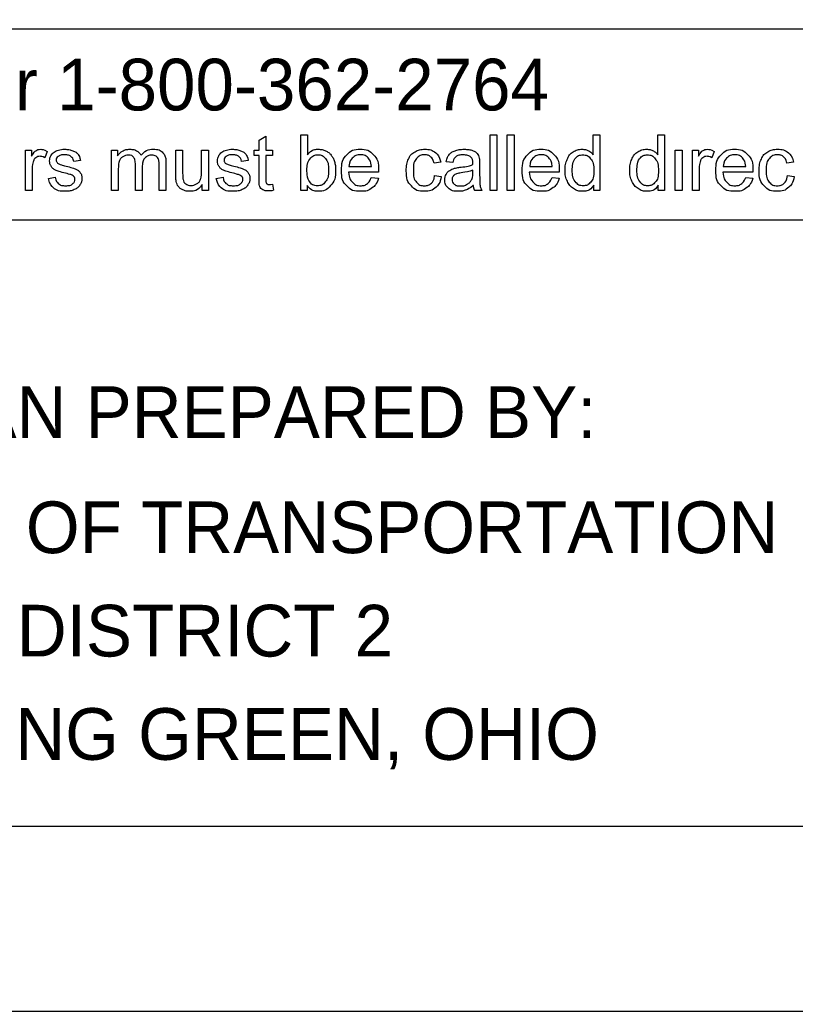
# Model space of a CAD drawing. Extents: x -5.6 to 34, y 0 to 22.
# Drawn here: x 4.575 to 6.676, y 0 to 2.686 of the extents above; entities that cross this region are included whole.
import ezdxf

# ---------------------------------------------------------------- set-up
doc = ezdxf.new("R2010")
doc.units = 0
for name, color, linetype in [('SH_Border', 7, 'Continuous'), ('SH_Cut_Line', 7, 'Continuous'), ('SH_Data', 7, 'Continuous'), ('SH_Text', 7, 'Continuous')]:
    doc.layers.add(name, color=color, linetype=linetype)

msp = doc.modelspace()

# ---------------------------------------------------------------- linework, layer by layer
at = {"layer": 'SH_Border'}
msp.add_lwpolyline([(1.5, 21.5), (33.5, 21.5), (33.5, 0.5), (1.5, 0.5)], close=True, dxfattribs=at)
at = {"layer": 'SH_Cut_Line'}
msp.add_lwpolyline([(0, 0), (34, 0), (34, 22), (0, 22)], close=True, dxfattribs=at)
at = {"layer": 'SH_Data'}
for p, q in [((7.2275, 2.6607), (2.9775, 2.6607)), ((7.2275, 2.1428), (2.9775, 2.1428))]:
    msp.add_line(p, q, dxfattribs=at)
at = {"layer": 'SH_Text'}
for points in [[(5.2233, 2.2558), (5.2233, 2.3185), (5.2097, 2.3185), (5.2097, 2.3328), (5.2233, 2.3328), (5.2233, 2.3597), (5.2417, 2.3708), (5.2417, 2.3328), (5.2601, 2.3328), (5.2601, 2.3185), (5.2417, 2.3185), (5.2417, 2.2547)], [(5.3534, 2.2239), (5.3363, 2.2239), (5.3363, 2.3741), (5.3548, 2.3741), (5.3548, 2.3206)], [(5.8491, 2.2239), (5.8491, 2.3741), (5.8675, 2.3741), (5.8675, 2.2239), (5.8491, 2.2239)], [(5.8956, 2.2239), (5.8956, 2.3741), (5.9141, 2.3741), (5.9141, 2.2239), (5.8956, 2.2239)], [(6.1285, 2.3202), (6.1285, 2.3741), (6.1469, 2.3741), (6.1469, 2.2239), (6.1299, 2.2239)], [(6.3034, 2.3202), (6.3034, 2.3741), (6.3218, 2.3741), (6.3218, 2.2239), (6.3048, 2.2239)], [(4.5904, 2.2239), (4.5904, 2.3328), (4.607, 2.3328), (4.607, 2.3163)], [(4.6495, 2.3293), (4.643, 2.3122)], [(4.8236, 2.2239), (4.8236, 2.3328), (4.8401, 2.3328), (4.8401, 2.3174)], [(4.9979, 2.2654), (4.9979, 2.3328), (5.0164, 2.3328), (5.0164, 2.2724)], [(5.0676, 2.2745), (5.0676, 2.3328), (5.0861, 2.3328), (5.0861, 2.2239), (5.0696, 2.2239)], [(6.3509, 2.2239), (6.3509, 2.3328), (6.3693, 2.3328), (6.3693, 2.2239), (6.3509, 2.2239)], [(6.3971, 2.2239), (6.3971, 2.3328), (6.4137, 2.3328), (6.4137, 2.3163)], [(6.4562, 2.3293), (6.4497, 2.3122)], [(4.7394, 2.3046), (4.7213, 2.3022)], [(4.9067, 2.2871), (4.9067, 2.2239), (4.8883, 2.2239), (4.8883, 2.2946)], [(4.9711, 2.2986), (4.9711, 2.2239), (4.9527, 2.2239), (4.9527, 2.2924)], [(5.194, 2.3046), (5.1759, 2.3022)], [(5.4669, 2.2887), (5.5277, 2.2887)], [(5.7154, 2.3007), (5.6974, 2.298)], [(5.7479, 2.2992), (5.7298, 2.3016)], [(5.8209, 2.2941), (5.8209, 2.2695)], [(5.9565, 2.2887), (6.0173, 2.2887)], [(6.481, 2.2887), (6.5418, 2.2887)], [(6.6712, 2.3007), (6.6532, 2.298)], [(4.6088, 2.2809), (4.6088, 2.2239), (4.5904, 2.2239)], [(4.653, 2.2564), (4.6712, 2.2593)], [(4.842, 2.2803), (4.842, 2.2239), (4.8236, 2.2239)], [(5.1076, 2.2564), (5.1258, 2.2593)], [(5.547, 2.2736), (5.4659, 2.2736)], [(5.5275, 2.2591), (5.5465, 2.2567)], [(5.699, 2.2638), (5.7171, 2.2613)], [(5.8023, 2.2718), (5.8024, 2.2785)], [(6.0366, 2.2736), (5.9555, 2.2736)], [(6.0171, 2.2591), (6.0361, 2.2567)], [(6.4155, 2.2809), (6.4155, 2.2239), (6.3971, 2.2239)], [(6.5611, 2.2736), (6.48, 2.2736)], [(6.5416, 2.2591), (6.5606, 2.2567)], [(6.6548, 2.2638), (6.6729, 2.2613)], [(5.0696, 2.2239), (5.0696, 2.24)], [(5.2601, 2.2404), (5.2628, 2.2241)], [(5.3534, 2.2375), (5.3534, 2.2239)], [(6.1299, 2.2239), (6.1299, 2.2376)], [(6.3048, 2.2239), (6.3048, 2.2376)], [(5.8267, 2.2239), (5.8075, 2.2239)]]:
    msp.add_lwpolyline(points, dxfattribs=at)
for points, degree in [([(4.607, 2.3163), (4.6133, 2.3278), (4.6187, 2.3315), (4.6241, 2.3352), (4.6305, 2.3352), (4.6398, 2.3352), (4.6495, 2.3293)], 3), ([(4.643, 2.3122), (4.6363, 2.3162), (4.6295, 2.3162), (4.6235, 2.3162), (4.6187, 2.3125), (4.6139, 2.3089), (4.6119, 2.3024), (4.6088, 2.2926), (4.6088, 2.2809)], 3), ([(4.7213, 2.3022), (4.7201, 2.3106), (4.7142, 2.3153), (4.7083, 2.3201), (4.6975, 2.3201), (4.6848, 2.3201), (4.6794, 2.3159), (4.6739, 2.3116), (4.6739, 2.306), (4.6739, 2.3024), (4.6762, 2.2995), (4.6785, 2.2966), (4.6833, 2.2946), (4.686, 2.2936), (4.6996, 2.2899), (4.7192, 2.2847), (4.7269, 2.2813), (4.7347, 2.278), (4.7391, 2.2717), (4.7435, 2.2653), (4.7435, 2.2559), (4.7435, 2.2467), (4.7381, 2.2386), (4.7327, 2.2304), (4.7226, 2.226), (4.7124, 2.2215), (4.6996, 2.2215), (4.6784, 2.2215), (4.6672, 2.2303), (4.6561, 2.2391), (4.653, 2.2564)], 3), ([(4.6712, 2.2593), (4.6727, 2.2483), (4.6798, 2.2425), (4.6868, 2.2366), (4.6995, 2.2366), (4.7122, 2.2366), (4.7184, 2.2418), (4.7245, 2.247), (4.7245, 2.254), (4.7245, 2.2602), (4.7191, 2.2638), (4.7153, 2.2663), (4.7002, 2.2701), (4.6799, 2.2752), (4.672, 2.2789), (4.6642, 2.2827), (4.6601, 2.2893), (4.6561, 2.2959), (4.6561, 2.3038), (4.6561, 2.3111), (4.6594, 2.3173), (4.6628, 2.3235), (4.6685, 2.3276), (4.6728, 2.3308), (4.6803, 2.333), (4.6877, 2.3352), (4.6962, 2.3352), (4.709, 2.3352), (4.7187, 2.3315), (4.7284, 2.3278), (4.733, 2.3215), (4.7377, 2.3152), (4.7394, 2.3046)], 3), ([(4.8401, 2.3174), (4.8452, 2.3254), (4.8537, 2.3303), (4.8622, 2.3352), (4.8731, 2.3352), (4.8852, 2.3352), (4.8929, 2.3301), (4.9007, 2.3251), (4.9038, 2.3161), (4.9168, 2.3352), (4.9375, 2.3352), (4.9537, 2.3352), (4.9624, 2.3262), (4.9711, 2.3172), (4.9711, 2.2986)], 3), ([(4.8883, 2.2946), (4.8883, 2.3069), (4.8838, 2.313), (4.8793, 2.3191), (4.869, 2.3191), (4.8612, 2.3191), (4.8546, 2.315), (4.848, 2.311), (4.845, 2.3031), (4.842, 2.2952), (4.842, 2.2803)], 3), ([(4.9527, 2.2924), (4.9527, 2.3035), (4.9509, 2.3083), (4.9491, 2.3132), (4.9444, 2.3162), (4.9397, 2.3191), (4.9333, 2.3191), (4.9219, 2.3191), (4.9143, 2.3115), (4.9067, 2.3039), (4.9067, 2.2871)], 3), ([(5.1759, 2.3022), (5.1747, 2.3106), (5.1688, 2.3153), (5.1629, 2.3201), (5.1521, 2.3201), (5.1394, 2.3201), (5.1339, 2.3159), (5.1285, 2.3116), (5.1285, 2.306), (5.1285, 2.3024), (5.1308, 2.2995), (5.133, 2.2966), (5.1378, 2.2946), (5.1406, 2.2936), (5.1542, 2.2899), (5.1737, 2.2847), (5.1815, 2.2813), (5.1893, 2.278), (5.1937, 2.2717), (5.1981, 2.2653), (5.1981, 2.2559), (5.1981, 2.2467), (5.1927, 2.2386), (5.1873, 2.2304), (5.1772, 2.226), (5.167, 2.2215), (5.1542, 2.2215), (5.1329, 2.2215), (5.1218, 2.2303), (5.1107, 2.2391), (5.1076, 2.2564)], 3), ([(5.1258, 2.2593), (5.1273, 2.2483), (5.1343, 2.2425), (5.1414, 2.2366), (5.154, 2.2366), (5.1668, 2.2366), (5.1729, 2.2418), (5.1791, 2.247), (5.1791, 2.254), (5.1791, 2.2602), (5.1736, 2.2638), (5.1698, 2.2663), (5.1548, 2.2701), (5.1345, 2.2752), (5.1266, 2.2789), (5.1188, 2.2827), (5.1147, 2.2893), (5.1107, 2.2959), (5.1107, 2.3038), (5.1107, 2.3111), (5.114, 2.3173), (5.1173, 2.3235), (5.1231, 2.3276), (5.1274, 2.3308), (5.1348, 2.333), (5.1423, 2.3352), (5.1508, 2.3352), (5.1636, 2.3352), (5.1733, 2.3315), (5.183, 2.3278), (5.1876, 2.3215), (5.1922, 2.3152), (5.194, 2.3046)], 3), ([(5.3532, 2.2792), (5.3532, 2.2596), (5.3585, 2.2509), (5.3672, 2.2366), (5.382, 2.2366), (5.3941, 2.2366), (5.4029, 2.2471), (5.4116, 2.2576), (5.4116, 2.2784), (5.4116, 2.2998), (5.4032, 2.3099), (5.3948, 2.3201), (5.3828, 2.3201), (5.3708, 2.3201), (5.362, 2.3096), (5.3532, 2.299), (5.3532, 2.2792)], 3), ([(5.3548, 2.3206), (5.3664, 2.3352), (5.3846, 2.3352), (5.3946, 2.3352), (5.4036, 2.3311), (5.4125, 2.3271), (5.4183, 2.3198), (5.4241, 2.3124), (5.4274, 2.3021), (5.4306, 2.2918), (5.4306, 2.28), (5.4306, 2.252), (5.4168, 2.2368), (5.403, 2.2215), (5.3836, 2.2215), (5.3644, 2.2215), (5.3534, 2.2375)], 3), ([(5.5465, 2.2567), (5.542, 2.24), (5.5298, 2.2307), (5.5177, 2.2215), (5.4987, 2.2215), (5.4749, 2.2215), (5.4609, 2.2362), (5.4469, 2.2509), (5.4469, 2.2774), (5.4469, 2.3049), (5.461, 2.32), (5.4752, 2.3352), (5.4977, 2.3352), (5.5195, 2.3352), (5.5333, 2.3203), (5.5471, 2.3055), (5.5471, 2.2785), (5.5471, 2.2769), (5.547, 2.2736)], 3), ([(5.5277, 2.2887), (5.5265, 2.3025), (5.5207, 2.3094), (5.5119, 2.3201), (5.4979, 2.3201), (5.4852, 2.3201), (5.4765, 2.3115), (5.4678, 2.303), (5.4669, 2.2887)], 3), ([(5.7171, 2.2613), (5.7141, 2.2427), (5.7019, 2.2321), (5.6896, 2.2215), (5.6718, 2.2215), (5.6495, 2.2215), (5.6359, 2.2361), (5.6223, 2.2507), (5.6223, 2.2779), (5.6223, 2.2955), (5.6282, 2.3088), (5.634, 2.322), (5.646, 2.3286), (5.6579, 2.3352), (5.6719, 2.3352), (5.6897, 2.3352), (5.7009, 2.3262), (5.7122, 2.3172), (5.7154, 2.3007)], 3), ([(5.6974, 2.298), (5.6949, 2.309), (5.6884, 2.3145), (5.6819, 2.3201), (5.6726, 2.3201), (5.6587, 2.3201), (5.65, 2.3101), (5.6413, 2.3001), (5.6413, 2.2784), (5.6413, 2.2565), (5.6497, 2.2466), (5.6581, 2.2366), (5.6717, 2.2366), (5.6825, 2.2366), (5.6898, 2.2433), (5.6971, 2.2499), (5.699, 2.2638)], 3), ([(5.8038, 2.2373), (5.7936, 2.2287), (5.7841, 2.2251), (5.7746, 2.2215), (5.7638, 2.2215), (5.7458, 2.2215), (5.7362, 2.2303), (5.7266, 2.239), (5.7266, 2.2526), (5.7266, 2.2606), (5.7302, 2.2672), (5.7339, 2.2738), (5.7398, 2.2778), (5.7456, 2.2818), (5.753, 2.2838), (5.7584, 2.2853), (5.7694, 2.2866), (5.7917, 2.2893), (5.8023, 2.2929), (5.8024, 2.2967), (5.8024, 2.2978), (5.8024, 2.3091), (5.7971, 2.3137), (5.7901, 2.3199), (5.7762, 2.3199), (5.7632, 2.3199), (5.757, 2.3154), (5.7508, 2.3108), (5.7479, 2.2992)], 3), ([(5.7298, 2.3016), (5.7323, 2.3132), (5.7379, 2.3203), (5.7435, 2.3275), (5.7542, 2.3313), (5.7648, 2.3352), (5.7788, 2.3352), (5.7928, 2.3352), (5.8015, 2.3319), (5.8102, 2.3286), (5.8142, 2.3236), (5.8183, 2.3187), (5.82, 2.3111), (5.8209, 2.3064), (5.8209, 2.2941)], 3), ([(6.0361, 2.2567), (6.0316, 2.24), (6.0194, 2.2307), (6.0072, 2.2215), (5.9883, 2.2215), (5.9644, 2.2215), (5.9505, 2.2362), (5.9365, 2.2509), (5.9365, 2.2774), (5.9365, 2.3049), (5.9506, 2.32), (5.9648, 2.3352), (5.9873, 2.3352), (6.0091, 2.3352), (6.0229, 2.3203), (6.0367, 2.3055), (6.0367, 2.2785), (6.0367, 2.2769), (6.0366, 2.2736)], 3), ([(6.0173, 2.2887), (6.0161, 2.3025), (6.0103, 2.3094), (6.0015, 2.3201), (5.9875, 2.3201), (5.9748, 2.3201), (5.9661, 2.3115), (5.9574, 2.303), (5.9565, 2.2887)], 3), ([(6.1299, 2.2376), (6.1195, 2.2215), (6.0995, 2.2215), (6.0865, 2.2215), (6.0755, 2.2287), (6.0646, 2.2359), (6.0586, 2.2487), (6.0526, 2.2616), (6.0526, 2.2782), (6.0526, 2.2945), (6.0581, 2.3078), (6.0635, 2.321), (6.0743, 2.3281), (6.0852, 2.3352), (6.0986, 2.3352), (6.1084, 2.3352), (6.116, 2.331), (6.1237, 2.3269), (6.1285, 2.3202)], 3), ([(6.0716, 2.2782), (6.0716, 2.2573), (6.0805, 2.247), (6.0893, 2.2366), (6.1012, 2.2366), (6.1133, 2.2366), (6.1218, 2.2465), (6.1302, 2.2564), (6.1302, 2.2767), (6.1302, 2.299), (6.1216, 2.3095), (6.113, 2.3199), (6.1004, 2.3199), (6.0881, 2.3199), (6.0799, 2.3099), (6.0716, 2.2999), (6.0716, 2.2782)], 3), ([(6.3048, 2.2376), (6.2944, 2.2215), (6.2743, 2.2215), (6.2613, 2.2215), (6.2504, 2.2287), (6.2395, 2.2359), (6.2335, 2.2487), (6.2275, 2.2616), (6.2275, 2.2782), (6.2275, 2.2945), (6.2329, 2.3078), (6.2384, 2.321), (6.2492, 2.3281), (6.26, 2.3352), (6.2734, 2.3352), (6.2832, 2.3352), (6.2909, 2.331), (6.2986, 2.3269), (6.3034, 2.3202)], 3), ([(6.2465, 2.2782), (6.2465, 2.2573), (6.2553, 2.247), (6.2641, 2.2366), (6.2761, 2.2366), (6.2882, 2.2366), (6.2967, 2.2465), (6.3051, 2.2564), (6.3051, 2.2767), (6.3051, 2.299), (6.2965, 2.3095), (6.2879, 2.3199), (6.2753, 2.3199), (6.263, 2.3199), (6.2548, 2.3099), (6.2465, 2.2999), (6.2465, 2.2782)], 3), ([(6.4137, 2.3163), (6.4201, 2.3278), (6.4254, 2.3315), (6.4308, 2.3352), (6.4372, 2.3352), (6.4466, 2.3352), (6.4562, 2.3293)], 3), ([(6.4497, 2.3122), (6.443, 2.3162), (6.4363, 2.3162), (6.4302, 2.3162), (6.4255, 2.3125), (6.4207, 2.3089), (6.4186, 2.3024), (6.4155, 2.2926), (6.4155, 2.2809)], 3), ([(6.5606, 2.2567), (6.5561, 2.24), (6.5439, 2.2307), (6.5317, 2.2215), (6.5128, 2.2215), (6.4889, 2.2215), (6.475, 2.2362), (6.461, 2.2509), (6.461, 2.2774), (6.461, 2.3049), (6.4751, 2.32), (6.4892, 2.3352), (6.5118, 2.3352), (6.5336, 2.3352), (6.5474, 2.3203), (6.5612, 2.3055), (6.5612, 2.2785), (6.5612, 2.2769), (6.5611, 2.2736)], 3), ([(6.5418, 2.2887), (6.5405, 2.3025), (6.5348, 2.3094), (6.526, 2.3201), (6.512, 2.3201), (6.4993, 2.3201), (6.4906, 2.3115), (6.4819, 2.303), (6.481, 2.2887)], 3), ([(6.6729, 2.2613), (6.67, 2.2427), (6.6577, 2.2321), (6.6455, 2.2215), (6.6277, 2.2215), (6.6053, 2.2215), (6.5917, 2.2361), (6.5782, 2.2507), (6.5782, 2.2779), (6.5782, 2.2955), (6.584, 2.3088), (6.5899, 2.322), (6.6018, 2.3286), (6.6137, 2.3352), (6.6278, 2.3352), (6.6455, 2.3352), (6.6568, 2.3262), (6.668, 2.3172), (6.6712, 2.3007)], 3), ([(6.6532, 2.298), (6.6507, 2.309), (6.6442, 2.3145), (6.6377, 2.3201), (6.6285, 2.3201), (6.6146, 2.3201), (6.6059, 2.3101), (6.5972, 2.3001), (6.5972, 2.2784), (6.5972, 2.2565), (6.6056, 2.2466), (6.614, 2.2366), (6.6275, 2.2366), (6.6384, 2.2366), (6.6456, 2.2433), (6.6529, 2.2499), (6.6548, 2.2638)], 3), ([(5.0696, 2.24), (5.0569, 2.2215), (5.0351, 2.2215), (5.0255, 2.2215), (5.0171, 2.2252), (5.0088, 2.2289), (5.0047, 2.2345), (5.0007, 2.2401), (4.9991, 2.2482), (4.9979, 2.2536), (4.9979, 2.2654)], 3), ([(5.0164, 2.2724), (5.0164, 2.258), (5.0175, 2.253), (5.0192, 2.2457), (5.0249, 2.2416), (5.0305, 2.2374), (5.0388, 2.2374), (5.0471, 2.2374), (5.0543, 2.2417), (5.0616, 2.2459), (5.0646, 2.2533), (5.0676, 2.2606), (5.0676, 2.2745)], 3), ([(5.4659, 2.2736), (5.4669, 2.2557), (5.476, 2.2462), (5.4852, 2.2366), (5.4988, 2.2366), (5.5089, 2.2366), (5.5161, 2.242), (5.5233, 2.2473), (5.5275, 2.2591)], 3), ([(5.8024, 2.2785), (5.7923, 2.2744), (5.7722, 2.2716), (5.7608, 2.2699), (5.7561, 2.2679), (5.7514, 2.2658), (5.7488, 2.2619), (5.7463, 2.2579), (5.7463, 2.2531), (5.7463, 2.2458), (5.7519, 2.2409), (5.7574, 2.2359), (5.7682, 2.2359), (5.7788, 2.2359), (5.7871, 2.2406), (5.7954, 2.2453), (5.7993, 2.2533), (5.8023, 2.2596), (5.8023, 2.2718)], 3), ([(5.8209, 2.2695), (5.8209, 2.2438), (5.8221, 2.237), (5.8233, 2.2302), (5.8267, 2.2239)], 3), ([(5.9555, 2.2736), (5.9565, 2.2557), (5.9656, 2.2462), (5.9748, 2.2366), (5.9884, 2.2366), (5.9985, 2.2366), (6.0057, 2.242), (6.0129, 2.2473), (6.0171, 2.2591)], 3), ([(6.48, 2.2736), (6.481, 2.2557), (6.4901, 2.2462), (6.4992, 2.2366), (6.5129, 2.2366), (6.523, 2.2366), (6.5302, 2.242), (6.5374, 2.2473), (6.5416, 2.2591)], 3), ([(5.2628, 2.2241), (5.255, 2.2224), (5.2488, 2.2224), (5.2388, 2.2224), (5.2333, 2.2256), (5.2278, 2.2288), (5.2255, 2.234), (5.2233, 2.2392), (5.2233, 2.2558)], 3), ([(5.2417, 2.2547), (5.2417, 2.2468), (5.2427, 2.2445), (5.2436, 2.2423), (5.2458, 2.2409), (5.248, 2.2396), (5.2521, 2.2396), (5.2551, 2.2396), (5.2601, 2.2404)], 3), ([(5.8075, 2.2239), (5.8047, 2.2296), (5.8038, 2.2373)], 2)]:
    msp.add_open_spline(points, degree=degree, dxfattribs=at)

# ---------------------------------------------------------------- texts
for s, p in [('OHIO811, 8-1-1, or 1-800-362-2764', (3.022, 2.4406)), ('PLAN PREPARED BY:', (4.2125, 1.553)), ('OHIO DEPT. OF TRANSPORTATION', (3.4578, 1.241)), ('DISTRICT 2', (4.5671, 0.961)), ('BOWLING GREEN, OHIO', (3.9596, 0.681))]:
    msp.add_text(s, height=0.14, dxfattribs=at).set_placement(p)

doc.saveas('drawing.dxf')
